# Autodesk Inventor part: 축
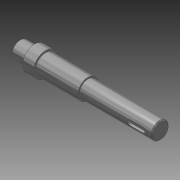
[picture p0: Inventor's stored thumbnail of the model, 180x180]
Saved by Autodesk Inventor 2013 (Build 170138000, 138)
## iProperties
Created: 2015-09
Part Number: 축
Material: 강철, 연강
Document SubType Name: Modeling
Designer: mduedu
Density: 7.86 g/cm^3
Mass: 263.424 g
Surface Area: 86.4309 cm^2
Volume: 33.5145 cm^3
Author: mduedu
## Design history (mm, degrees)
sketch "스케치1"
  geometry: L1 (-70, 0)-(70, 0); L2 (-70, 0)-(-70, 8.5); L3 (-70, 8.5)-(-55, 8.5); L4 (-55, 8.5)-(-55, 12); L5 (-55, 12)-(-44, 12); L6 (-44, 12)-(-44, 10); L7 (-44, 10)-(-2, 10); L8 (-2, 10)-(-2, 8.5); L9 (-2, 8.5)-(70, 8.5); L10 (70, 8.5)-(70, 0); 2 further points
  constraints: 20 end point, 5 parallel, 2 horizontal, 2 perpendicular, 1 coincident, 1 midpoint, 1 vertical
  dimensions: "d0" = 140 distance of L1.start L1.end; "d2" = 11 distance of L4.end L5.end; "d3" = 42 distance of L6.end L7.end; "d4" = 72 distance of L8.end L9.end; "d5" = 17 diameter of L3 L1; "d6" = 17 diameter of L9 L1; "d7" = 20 diameter of L7 L1; "d8" = 24 diameter of L5 L1
revolve "회전1" sketch "스케치1" stored, may be unused: angle "d9" = 90 deg
node "작업 평면1"
sketch "스케치2"
  geometry: L1 (13.5, 2.5)-(26.5, 2.5); L2 (26.5, -2.5)-(13.5, -2.5); L3 (13.5, 2.5)-(26.5, -2.5); L4 (26.5, 2.5)-(13.5, -2.5); L5 (36, -8.5)-(36, 8.5) reference; A1 r 2.5 centre (13.5, 0) between (13.5, 2.5) and (13.5, -2.5); A2 r 2.5 centre (26.5, 0) between (26.5, -2.5) and (26.5, 2.5); 2 further points
  constraints: 8 end point, 4 point on circle, 4 tangent, 2 centre point, 2 midpoint, 1 horizontal, 1 horizontal alignment, 1 parallel
  dimensions: "d10" = 18 dimension on A2 A1; "d12" = 7 distance edge to line of A2 L5; "d13" = 5 distance between parallel lines of L2 L1
extrude "돌출1" cut sketch "스케치2" distance "d14" = 3; taper "d15" = 0 deg
node "작업 평면2"
sketch "스케치4"
  geometry: L1 (7, -3)-(-9, -3); L2 (-9, 3)-(7, 3); L3 (-21, 10)-(-21, -10) reference; A1 r 3 centre (-9, 0) between (-9, 3) and (-9, -3); A2 r 3 centre (7, 0) between (7, -3) and (7, 3); 1 further point
  constraints: 4 end point, 4 point on circle, 4 tangent, 2 centre point, 1 horizontal, 1 horizontal alignment, 1 parallel
  dimensions: "d16" = 22 dimension on A1 A2; "d18" = 6 distance between parallel lines of L2 L1; "d19" = 9 distance edge to line of A1 L3
extrude "돌출2" cut sketch "스케치4" distance "d20" = 3.5; taper "d21" = 0 deg
sketch "스케치5"
  geometry: L1 (-2, 8.5)-(70, 8.5) reference; L2 (-2, -8.5)-(70, -8.5) reference; L3 (43, 8.5)-(43, -8.5); L4 (43, -6.5)-(41, -8.5); L5 (43, -8.5)-(41, -8.5); L6 (43, -8.5)-(43, -6.5); L7 (-2, -10)-(-2, 10) reference; 1 further point
  constraints: 8 end point, 4 point on line, 1 collinear, 1 perpendicular
  dimensions: "d22" = 4 diameter of L4.end L3; "d24" = 45 deg angle of L3 L4; "d26" = 45 distance between parallel lines of L3 L7
revolve "회전2" sketch "스케치5" stored, may be unused: angle "d27" = 90 deg
chamfer "모따기1" distance "d28" = 1; stored, may be unused: second distance "d29" = 2, angle "d30" = 45 deg
sketch "스케치6"
  geometry: L1 (43, -6.5)-(41, -8.5) reference; L2 (43, -6.5)-(45, -8.5) reference; 2 further points
  constraints: 1 coincident
node "솔리드1"
